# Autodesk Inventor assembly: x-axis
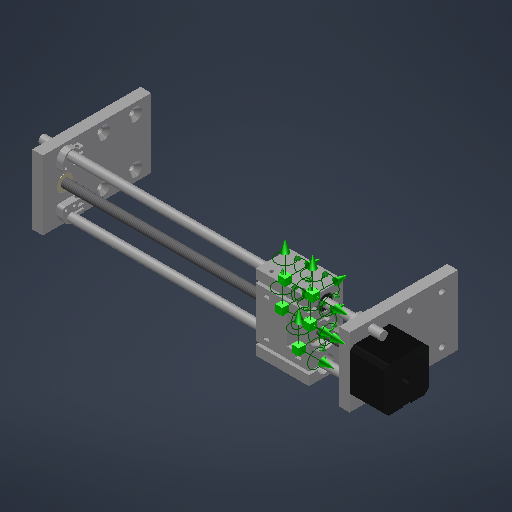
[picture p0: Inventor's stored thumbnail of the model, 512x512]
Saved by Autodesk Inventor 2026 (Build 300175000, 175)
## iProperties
Created: 2025-04
Part Number: x-axis
Material: Generisch
Document SubType Name: Assembly
Designer: BennF
Author: BennF
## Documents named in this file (10)
- C:\Users\BennF\Nextcloud\Benedikt\FabAcademy\week12\CAD\x-axis\x-axis.iam
- C:\Users\BennF\Nextcloud\Benedikt\FabAcademy\week12\CAD\x-axis\x_axis_mounting_plate_stepper.ipt
- C:\Users\BennF\Nextcloud\Benedikt\FabAcademy\week12\CAD\x-axis\x_axis_8mm_rod.ipt
- C:\Users\BennF\Nextcloud\Benedikt\FabAcademy\week12\CAD\x-axis\x_axis_mounting_plate.ipt
- C:\Users\BennF\Nextcloud\Benedikt\FabAcademy\week12\CAD\bushig_8mm.ipt
- C:\Users\BennF\Nextcloud\Benedikt\FabAcademy\week12\CAD\x-axis\x_axis_slate.ipt
- C:\Users\BennF\Nextcloud\Benedikt\FabAcademy\week12\CAD\t8_screw_nut_polymere.ipt
- C:\Users\BennF\Nextcloud\Benedikt\FabAcademy\week12\CAD\LM8UU.ipt
- C:\Users\BennF\Nextcloud\Benedikt\FabAcademy\week12\CAD\x-axis\stepper_Motor.ipt
- C:\Users\BennF\Nextcloud\Benedikt\FabAcademy\week12\CAD\x-axis\x_axis_8mm_rod_mount.ipt
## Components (16 placed, 9 different names)
1. x_axis_mounting_plate_stepper:1 — Insert:1, Insert:3, Insert:10, Insert:11, Insert:12, Insert:18
2. x_axis_mounting_plate:1 — Insert:2, Insert:4, Insert:5, Insert:13, Insert:14, Angle:1, Insert:19
3. x_axis_8mm_rod:1 — Insert:1, Insert:2, Cylindrical:1
4. x_axis_8mm_rod:2 — Insert:3, Insert:4
5. bushig_8mm:1 — Insert:5
6. x_axis_slate:1 — Insert:6, Insert:7, Insert:8, Insert:9, Insert:17, Angle:1
7. t8_screw_nut_polymere:1 — Insert:6
8. t8_screw_nut_polymere:2 — Insert:7
9. LM8UU:1 — Insert:8
10. LM8UU:2 — Insert:9, Cylindrical:1
11. LM8UU:3 — Insert:17
12. stepper_Motor:1 — Insert:10
13. x_axis_8mm_rod_mount:1 — Insert:11, Insert:18
14. x_axis_8mm_rod_mount:2 — Insert:12
15. x_axis_8mm_rod_mount:3 — Insert:13
16. x_axis_8mm_rod_mount:4 — Insert:14, Insert:19
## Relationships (19: Insert 17, CylindricalJoint 1, Angle 1)
- Insert:1: x_axis_mounting_plate_stepper:1 ↔ x_axis_8mm_rod:1
- Insert:2: x_axis_mounting_plate:1 ↔ x_axis_8mm_rod:1
- Insert:3: x_axis_mounting_plate_stepper:1 ↔ x_axis_8mm_rod:2
- Insert:4: x_axis_mounting_plate:1 ↔ x_axis_8mm_rod:2
- Insert:5: x_axis_mounting_plate:1 ↔ bushig_8mm:1
- Insert:6: x_axis_slate:1 ↔ t8_screw_nut_polymere:1
- Insert:7: x_axis_slate:1 ↔ t8_screw_nut_polymere:2
- Insert:8: x_axis_slate:1 ↔ LM8UU:1
- Insert:9: x_axis_slate:1 ↔ LM8UU:2
- Insert:17: x_axis_slate:1 ↔ LM8UU:3
- Cylindrical:1: x_axis_8mm_rod:1 ↔ LM8UU:2
- Insert:10: x_axis_mounting_plate_stepper:1 ↔ stepper_Motor:1
- Insert:11: x_axis_mounting_plate_stepper:1 ↔ x_axis_8mm_rod_mount:1
- Insert:12: x_axis_mounting_plate_stepper:1 ↔ x_axis_8mm_rod_mount:2
- Insert:13: x_axis_mounting_plate:1 ↔ x_axis_8mm_rod_mount:3
- Insert:14: x_axis_mounting_plate:1 ↔ x_axis_8mm_rod_mount:4
- Angle:1: x_axis_mounting_plate:1 ↔ x_axis_slate:1
- Insert:18: x_axis_mounting_plate_stepper:1 ↔ x_axis_8mm_rod_mount:1
- Insert:19: x_axis_mounting_plate:1 ↔ x_axis_8mm_rod_mount:4
